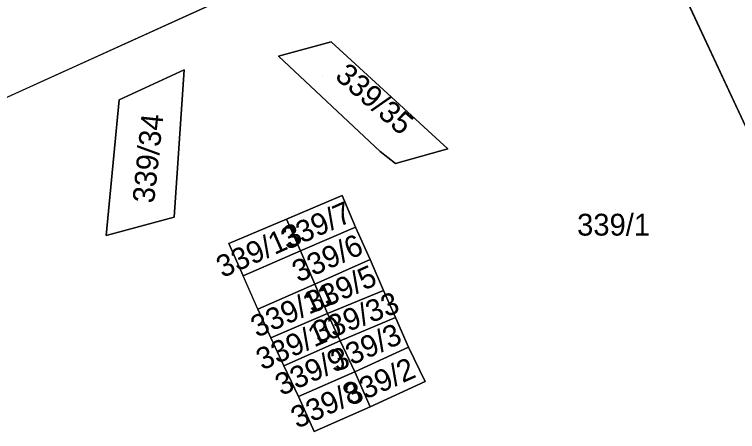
# Model space of a CAD drawing. Extents: x -264070 to -262271, y -1238894 to -1238141.
# Drawn here: x -263749.9 to -263683.6, y -1238577 to -1238538.8 of the extents above; entities that cross this region are included whole.
import ezdxf

# ---------------------------------------------------------------- set-up
doc = ezdxf.new("R2010")
doc.units = 0
for name, color, linetype in [('body_kn', 7, 'Continuous'), ('kladpar_druhypozemkov', 7, 'Continuous'), ('kladpar_hranice', 7, 'Continuous'), ('kladpar_parcelnecisla', 7, 'Continuous'), ('kladpar_plochy', 7, 'Continuous'), ('zappar_hrandruhpozemk', 7, 'Continuous')]:
    doc.layers.add(name, color=color, linetype=linetype)

msp = doc.modelspace()

# ---------------------------------------------------------------- linework, layer by layer
at = {"layer": 'body_kn'}
for p, q in [((-263720.84, -1238541.28), (-263720.84, -1238541.28)), ((-263725.65, -1238542.6), (-263725.65, -1238542.6)), ((-263725.65, -1238542.6), (-263725.65, -1238542.6)), ((-263734.3, -1238543.84), (-263734.3, -1238543.84)), ((-263740.28, -1238546.58), (-263740.28, -1238546.58)), ((-263740.28, -1238546.58), (-263740.28, -1238546.58)), ((-263710.14, -1238551.09), (-263710.14, -1238551.09)), ((-263716.34, -1238551.34), (-263716.34, -1238551.34)), ((-263714.93, -1238552.42), (-263714.93, -1238552.42)), ((-263719.81, -1238555.36), (-263719.81, -1238555.36)), ((-263719.81, -1238555.36), (-263719.81, -1238555.36)), ((-263735.22, -1238557.34), (-263735.22, -1238557.34)), ((-263724.91, -1238557.54), (-263724.91, -1238557.54)), ((-263724.91, -1238557.54), (-263724.91, -1238557.54)), ((-263718.6, -1238558.26), (-263718.6, -1238558.26)), ((-263718.6, -1238558.26), (-263718.6, -1238558.26)), ((-263741.47, -1238559.03), (-263741.47, -1238559.03)), ((-263730.2, -1238559.75), (-263730.2, -1238559.75)), ((-263723.64, -1238560.44), (-263723.64, -1238560.44)), ((-263717.26, -1238561.24), (-263717.26, -1238561.24)), ((-263717.26, -1238561.24), (-263717.26, -1238561.24)), ((-263728.89, -1238562.74), (-263728.89, -1238562.74)), ((-263722.33, -1238563.49), (-263722.33, -1238563.49)), ((-263722.33, -1238563.49), (-263722.33, -1238563.49)), ((-263716.04, -1238564.07), (-263716.04, -1238564.07)), ((-263727.56, -1238565.78), (-263727.56, -1238565.78)), ((-263727.56, -1238565.78), (-263727.56, -1238565.78)), ((-263721.18, -1238566.18), (-263721.18, -1238566.18)), ((-263721.18, -1238566.18), (-263721.18, -1238566.18)), ((-263714.94, -1238566.55), (-263714.94, -1238566.55)), ((-263714.94, -1238566.55), (-263714.94, -1238566.55)), ((-263726.37, -1238568.42), (-263726.37, -1238568.42)), ((-263720.01, -1238568.68), (-263720.01, -1238568.68)), ((-263720.01, -1238568.68), (-263720.01, -1238568.68)), ((-263713.75, -1238569.28), (-263713.75, -1238569.28)), ((-263713.75, -1238569.28), (-263713.75, -1238569.28)), ((-263725.17, -1238570.97), (-263725.17, -1238570.97)), ((-263718.67, -1238571.52), (-263718.67, -1238571.52)), ((-263718.67, -1238571.52), (-263718.67, -1238571.52)), ((-263712.2, -1238572.43), (-263712.2, -1238572.43)), ((-263723.82, -1238573.79), (-263723.82, -1238573.79)), ((-263717.24, -1238574.73), (-263717.24, -1238574.73)), ((-263722.38, -1238577.01), (-263722.38, -1238577.01))]:
    msp.add_line(p, q, dxfattribs=at)
at = {"layer": 'kladpar_druhypozemkov'}
for p, q in [((-263721.6, -1238544.33), (-263721.6, -1238544.33)), ((-263739.06, -1238552.39), (-263739.06, -1238552.39)), ((-263694.79, -1238556.69), (-263694.79, -1238556.69)), ((-263722.07, -1238557.28), (-263722.07, -1238557.28)), ((-263727.22, -1238559.25), (-263727.22, -1238559.25)), ((-263720.99, -1238559.97), (-263720.99, -1238559.97)), ((-263719.61, -1238562.79), (-263719.61, -1238562.79)), ((-263724.85, -1238565.16), (-263724.85, -1238565.16)), ((-263718.31, -1238565.43), (-263718.31, -1238565.43)), ((-263723.55, -1238567.9), (-263723.55, -1238567.9)), ((-263717.19, -1238568.35), (-263717.19, -1238568.35)), ((-263722.16, -1238570.5), (-263722.16, -1238570.5)), ((-263716.11, -1238571.35), (-263716.11, -1238571.35)), ((-263721.17, -1238573.5), (-263721.17, -1238573.5))]:
    msp.add_line(p, q, dxfattribs=at)
at = {"layer": 'kladpar_hranice'}
msp.add_line((-263753.82, -1238547.84), (-263730.52, -1238537.23), dxfattribs=at)
for points in [[(-263699.62, -1238523.38), (-263699, -1238521.97), (-263699.78, -1238520.3), (-263696.36, -1238518.7), (-263695.58, -1238518.33), (-263694.04, -1238519.09), (-263693.41, -1238520.47), (-263694.84, -1238521.21), (-263695.1, -1238522.64), (-263690.15, -1238533.34), (-263682.18, -1238550.43)], [(-263735.12, -1238526.44), (-263730.52, -1238537.23), (-263753.82, -1238547.84), (-263757.99, -1238537.04), (-263750.24, -1238533.62), (-263750, -1238534.47), (-263746.59, -1238532.94), (-263746.9, -1238531.93), (-263735.12, -1238526.44)], [(-263675.05, -1238537.69), (-263675.88, -1238538.05), (-263674.89, -1238540.23), (-263674.08, -1238539.86), (-263671.4, -1238545.46), (-263682.18, -1238550.43), (-263690.15, -1238533.34), (-263679.5, -1238528.24), (-263675.05, -1238537.69)], [(-263725.65, -1238542.6), (-263720.84, -1238541.28), (-263710.14, -1238551.09), (-263714.93, -1238552.42), (-263716.34, -1238551.34), (-263725.65, -1238542.6)], [(-263725.65, -1238542.6), (-263716.34, -1238551.34), (-263714.93, -1238552.42), (-263710.14, -1238551.09), (-263720.84, -1238541.28), (-263725.65, -1238542.6)], [(-263740.28, -1238546.58), (-263734.3, -1238543.84), (-263735.22, -1238557.34), (-263741.47, -1238559.03), (-263740.28, -1238546.58)], [(-263740.28, -1238546.58), (-263741.47, -1238559.03), (-263735.22, -1238557.34), (-263734.3, -1238543.84), (-263740.28, -1238546.58)], [(-263712.2, -1238572.43), (-263713.75, -1238569.28), (-263714.94, -1238566.55), (-263716.04, -1238564.07), (-263717.26, -1238561.24), (-263718.6, -1238558.26), (-263719.81, -1238555.36), (-263724.91, -1238557.54), (-263730.2, -1238559.75), (-263728.89, -1238562.74), (-263723.64, -1238560.44), (-263722.33, -1238563.49), (-263727.56, -1238565.78), (-263726.37, -1238568.42), (-263725.17, -1238570.97), (-263723.82, -1238573.79), (-263722.38, -1238577.01), (-263717.24, -1238574.73), (-263712.2, -1238572.43)], [(-263719.81, -1238555.36), (-263718.6, -1238558.26), (-263723.64, -1238560.44), (-263724.91, -1238557.54), (-263719.81, -1238555.36)], [(-263724.91, -1238557.54), (-263723.64, -1238560.44), (-263728.89, -1238562.74), (-263730.2, -1238559.75), (-263724.91, -1238557.54)], [(-263718.6, -1238558.26), (-263717.26, -1238561.24), (-263722.33, -1238563.49), (-263723.64, -1238560.44), (-263718.6, -1238558.26)], [(-263717.26, -1238561.24), (-263716.04, -1238564.07), (-263721.18, -1238566.18), (-263722.33, -1238563.49), (-263717.26, -1238561.24)], [(-263722.33, -1238563.49), (-263721.18, -1238566.18), (-263726.37, -1238568.42), (-263727.56, -1238565.78), (-263722.33, -1238563.49)], [(-263714.94, -1238566.55), (-263720.01, -1238568.68), (-263721.18, -1238566.18), (-263716.04, -1238564.07), (-263714.94, -1238566.55)], [(-263721.18, -1238566.18), (-263720.01, -1238568.68), (-263725.17, -1238570.97), (-263726.37, -1238568.42), (-263721.18, -1238566.18)], [(-263714.94, -1238566.55), (-263713.75, -1238569.28), (-263718.67, -1238571.52), (-263720.01, -1238568.68), (-263714.94, -1238566.55)], [(-263720.01, -1238568.68), (-263718.67, -1238571.52), (-263723.82, -1238573.79), (-263725.17, -1238570.97), (-263720.01, -1238568.68)], [(-263713.75, -1238569.28), (-263712.2, -1238572.43), (-263717.24, -1238574.73), (-263718.67, -1238571.52), (-263713.75, -1238569.28)], [(-263718.67, -1238571.52), (-263717.24, -1238574.73), (-263722.38, -1238577.01), (-263723.82, -1238573.79), (-263718.67, -1238571.52)]]:
    msp.add_lwpolyline(points, dxfattribs=at)
at = {"layer": 'kladpar_plochy'}
for p, q in [((-263690.15, -1238533.34), (-263682.18, -1238550.43)), ((-263753.82, -1238547.84), (-263730.52, -1238537.23)), ((-263720.84, -1238541.28), (-263725.65, -1238542.6)), ((-263710.14, -1238551.09), (-263720.84, -1238541.28)), ((-263725.65, -1238542.6), (-263716.34, -1238551.34)), ((-263734.3, -1238543.84), (-263740.28, -1238546.58)), ((-263735.22, -1238557.34), (-263734.3, -1238543.84)), ((-263740.28, -1238546.58), (-263741.47, -1238559.03)), ((-263714.93, -1238552.42), (-263710.14, -1238551.09)), ((-263716.34, -1238551.34), (-263714.93, -1238552.42)), ((-263719.81, -1238555.36), (-263724.91, -1238557.54)), ((-263718.6, -1238558.26), (-263719.81, -1238555.36)), ((-263741.47, -1238559.03), (-263735.22, -1238557.34)), ((-263724.91, -1238557.54), (-263730.2, -1238559.75)), ((-263717.26, -1238561.24), (-263718.6, -1238558.26)), ((-263730.2, -1238559.75), (-263728.89, -1238562.74)), ((-263728.89, -1238562.74), (-263723.64, -1238560.44)), ((-263723.64, -1238560.44), (-263722.33, -1238563.49)), ((-263716.04, -1238564.07), (-263717.26, -1238561.24)), ((-263722.33, -1238563.49), (-263727.56, -1238565.78)), ((-263714.94, -1238566.55), (-263716.04, -1238564.07)), ((-263727.56, -1238565.78), (-263726.37, -1238568.42)), ((-263713.75, -1238569.28), (-263714.94, -1238566.55)), ((-263726.37, -1238568.42), (-263725.17, -1238570.97)), ((-263712.2, -1238572.43), (-263713.75, -1238569.28)), ((-263725.17, -1238570.97), (-263723.82, -1238573.79)), ((-263717.24, -1238574.73), (-263712.2, -1238572.43)), ((-263723.82, -1238573.79), (-263722.38, -1238577.01)), ((-263722.38, -1238577.01), (-263717.24, -1238574.73))]:
    msp.add_line(p, q, dxfattribs=at)
for points in [[(-263735.12, -1238526.44), (-263730.52, -1238537.23), (-263753.82, -1238547.84), (-263757.99, -1238537.04), (-263750.24, -1238533.62), (-263750, -1238534.47), (-263746.59, -1238532.94), (-263746.9, -1238531.93)], [(-263675.05, -1238537.69), (-263675.88, -1238538.05), (-263674.89, -1238540.23), (-263674.08, -1238539.86), (-263671.4, -1238545.46), (-263682.18, -1238550.43), (-263690.15, -1238533.34), (-263679.5, -1238528.24)], [(-263725.65, -1238542.6), (-263720.84, -1238541.28), (-263710.14, -1238551.09), (-263714.93, -1238552.42), (-263716.34, -1238551.34)], [(-263740.28, -1238546.58), (-263734.3, -1238543.84), (-263735.22, -1238557.34), (-263741.47, -1238559.03)], [(-263719.81, -1238555.36), (-263718.6, -1238558.26), (-263723.64, -1238560.44), (-263724.91, -1238557.54)], [(-263724.91, -1238557.54), (-263723.64, -1238560.44), (-263728.89, -1238562.74), (-263730.2, -1238559.75)], [(-263718.6, -1238558.26), (-263717.26, -1238561.24), (-263722.33, -1238563.49), (-263723.64, -1238560.44)], [(-263717.26, -1238561.24), (-263716.04, -1238564.07), (-263721.18, -1238566.18), (-263722.33, -1238563.49)], [(-263722.33, -1238563.49), (-263721.18, -1238566.18), (-263726.37, -1238568.42), (-263727.56, -1238565.78)], [(-263714.94, -1238566.55), (-263720.01, -1238568.68), (-263721.18, -1238566.18), (-263716.04, -1238564.07)], [(-263721.18, -1238566.18), (-263720.01, -1238568.68), (-263725.17, -1238570.97), (-263726.37, -1238568.42)], [(-263714.94, -1238566.55), (-263713.75, -1238569.28), (-263718.67, -1238571.52), (-263720.01, -1238568.68)], [(-263720.01, -1238568.68), (-263718.67, -1238571.52), (-263723.82, -1238573.79), (-263725.17, -1238570.97)], [(-263713.75, -1238569.28), (-263712.2, -1238572.43), (-263717.24, -1238574.73), (-263718.67, -1238571.52)], [(-263718.67, -1238571.52), (-263717.24, -1238574.73), (-263722.38, -1238577.01), (-263723.82, -1238573.79)]]:
    msp.add_lwpolyline(points, close=True, dxfattribs=at)
at = {"layer": 'zappar_hrandruhpozemk'}
msp.add_line((-263727.56, -1238565.78), (-263728.89, -1238562.74), dxfattribs=at)

# ---------------------------------------------------------------- texts
at = {"layer": 'kladpar_parcelnecisla'}
for s, rotation, p in [('339/35', 319, (-263720.58, -1238544.565)), ('339/34', 84, (-263737.065, -1238556.133)), ('339/7', 24, (-263724.867, -1238560.39)), ('339/13', 24, (-263730.79, -1238562.945)), ('339/6', 24, (-263723.84, -1238563.37)), ('339/5', 24, (-263722.591, -1238566.212)), ('339/11', 24, (-263727.633, -1238568.426)), ('339/33', 21, (-263722.052, -1238568.928)), ('339/10', 24, (-263727.146, -1238571.426)), ('339/3', 24, (-263720.304, -1238571.561)), ('339/9', 24, (-263725.4, -1238573.76)), ('339/2', 24, (-263719.039, -1238574.695)), ('339/8', 24, (-263723.952, -1238576.769))]:
    msp.add_text(s, height=2, rotation=rotation, dxfattribs=at).set_placement(p)
msp.add_text('339/1', height=2, dxfattribs=at).set_placement((-263698.284, -1238559.04))

doc.saveas('drawing.dxf')
